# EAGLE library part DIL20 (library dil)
SOCKET Dual In Line
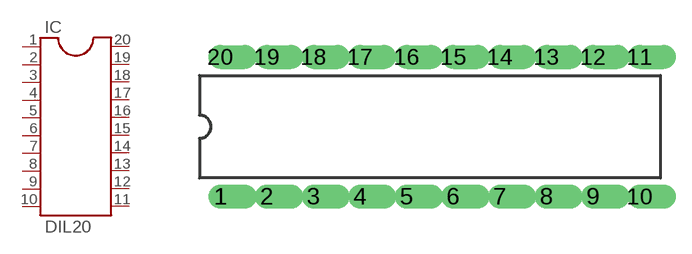
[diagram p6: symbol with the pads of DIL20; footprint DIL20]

Designator prefix IC

## DIL20  [DIL20]
1  1  pas
2  2  pas
3  3  pas
4  4  pas
5  5  pas
6  6  pas
7  7  pas
8  8  pas
9  9  pas
10  10  pas
11  11  pas
12  12  pas
13  13  pas
14  14  pas
15  15  pas
16  16  pas
17  17  pas
18  18  pas
19  19  pas
20  20  pas

## Footprint DIL20 (pad centres in mm)
SOCKET Dual In Line
drill 0.813 offset: 1 -11.43,-3.81; 2 -8.89,-3.81; 3 -6.35,-3.81; 4 -3.81,-3.81; 5 -1.27,-3.81; 6 1.27,-3.81; 7 3.81,-3.81; 8 6.35,-3.81; 9 8.89,-3.81; 10 11.43,-3.81; 11 11.43,3.81; 12 8.89,3.81; 13 6.35,3.81; 14 3.81,3.81; 15 1.27,3.81; 16 -1.27,3.81; 17 -3.81,3.81; 18 -6.35,3.81; 19 -8.89,3.81; 20 -11.43,3.81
